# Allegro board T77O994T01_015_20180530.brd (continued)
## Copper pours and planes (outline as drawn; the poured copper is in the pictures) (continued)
(no net) on P07: 28.72,23 28.72,55.58 47.07,73.93 86.34,73.93 88.68,71.59 94.42,71.59 95.02,72.2 95.56,72.2 96.31,71.45 105.4,71.45 106.19,70.66 106.19,61.86 104.28,59.96 102.38,59.96 99.2,63.13 93.49,63.13 91.58,61.23 91.58,40.8 96.61,35.77 96.61,29.88 94.93,28.19 91.57,28.19 82.06,18.68 37.89,18.68 37.55,18.84 37.21,18.68 33.04,18.68
(no net) on P07: 123.11,40 123.34,39.77 123.34,38.86 123.08,38.6 122.29,38.6 121.47,37.78 121.3,37.78 121.02,37.5 121.02,37.33 120.04,36.34 120.04,36.34 119.86,36.16 119.86,30.42 119.85,30.41 119.85,29.27 119.27,28.7 108.86,28.7 105.15,32.4 98.7,32.4 98.44,32.65 98.44,33.54 98.67,33.78 109.11,33.78 109.62,33.27 117.5,33.27 118.03,33.8 118.03,36.14 118.92,37.03 118.94,37.03 119.58,37.66 120.09,37.66 121.18,38.75 121.18,39.95 121.23,40 ; 2 cut-outs
(no net) on P07: 106.75,23.8 105.87,24.68 106.11,24.68 106.11,24.96 105.75,24.96 105.75,24.8 104.57,25.98 104.54,25.98 99.89,30.62 98.82,30.62 98.57,30.88 98.57,31.89 98.82,32.15 104.9,32.15 108.72,28.33 108.73,28.32 119.4,28.32 120.29,29.2 120.29,35.76 121.05,36.52 121.05,37.08 121.43,37.46 121.69,37.46 122.58,36.57 122.58,36.11 123.16,35.53 123.16,31.97 123.26,31.87 123.26,26.3 120.76,23.8 ; 3 cut-outs
(no net) on P07: 47.13,74.44 43.72,71.03 32.86,71.03 31.31,72.58 31.31,80.84 32.53,82.06 75.97,82.06 80.62,77.4 86.16,77.4 89.87,73.7 91.16,73.7 91.57,73.29 94.95,73.29 95.33,73.67 102.62,73.67 104.19,75.24 113.29,75.24 114.02,74.51 114.02,61.94 115.19,60.77 116.49,60.77 120.22,57.03 120.22,52.18 119.23,51.19 118.24,51.19 118.06,51.37 118.06,55.81 117.5,56.37 111.59,56.37 106.71,61.25 106.71,70.6 105.73,71.57 96.61,71.57 95.79,72.4 94.85,72.4 94.24,71.79 88.95,71.79 86.31,74.44 ; 2 cut-outs
(no net) on P07: 107.85,50.31 118.26,50.31 118.51,50.06 118.51,45.04 114.1,40.63 103.02,40.63 102.76,40.38 102.76,40.36 101.62,39.22 94.63,39.22 93.68,40.17 93.68,54.65 94.29,55.26 98.7,55.26 99.14,54.81 99.14,54.8 102.31,51.63 102.31,48.11 102.56,47.86 105.4,47.86
(no net) on P07: 75.52,82.78 20.56,82.78 15.79,78.01 15.79,53.75 17.87,51.67 25.64,51.67 26.81,50.5 26.81,22.13 26.47,21.79 24.92,21.79 22.64,19.51 22.64,19.16 19.33,15.85 19.33,13.3 19.83,12.8 19.83,6.62 16.02,6.62 16.02,13.4 15.24,14.18 15.24,15.38 15.25,15.39 15.25,17.55 12.21,20.59 2.05,30.75 2.05,77.74 18.81,94.5 78.23,94.5 79.28,93.46 79.28,86.6 76.15,83.47 75.52,82.84
(no net) on T08: 117.32,50.26 114.68,50.26 114.68,48.97 117.32,48.97
(no net) on T08: 121.59,37.94 121.28,37.94 121.08,38.15 121.08,38.68 121.13,38.73 121.13,39.16 121.08,39.21 121.08,39.75 121.26,39.92 123.16,39.92 123.24,39.85 123.24,39.49 123.03,39.29 122.8,39.29 121.89,38.37 121.89,38.25
(no net) on T08: 118.08,55.21 114.68,55.21 114.68,53.83 114.73,53.77 116.02,53.77 116.3,53.49 116.3,52.16 115.99,51.86 115.74,51.86 115.6,51.71 115.6,51.15 115.44,51 114.78,51 114.68,50.89 114.68,50.64 118.08,50.64
(no net) on T08: 121.13,40.41 121.31,40.23 123.21,40.23 123.49,39.95 123.49,39.36 121.76,37.64 121.33,37.64 120.87,37.18 120.87,36.75 120.32,36.19 120.32,33.75 120.57,33.5 122.35,33.5 122.36,33.51 122.72,33.51 122.98,33.78 122.98,36.06 122.97,36.08 122.97,36.58 123.22,36.84 123.5,36.84 124.4,37.74 124.4,38.02 124.53,38.15 124.53,39.29 124.89,39.64 124.89,40.66 124.61,40.94 121.2,40.94 121.13,40.86
(no net) on T08: 197.58,9.69 195.04,12.23 190.59,12.23 189.74,11.37 186.37,11.37 186.15,11.59 186.15,17.31 195.04,26.2 196.94,26.2 198.21,24.93 199.48,24.93 201.39,26.83 201.39,32.55 198.85,35.09 193.77,35.09 191.86,36.99 191.86,38.9 192.5,39.53 197.58,39.53 198.85,38.26 201.39,38.26 205.2,34.45 205.2,27.47 198.85,21.12 198.85,12.23 199.48,11.59 199.48,9.69 ; 1 cut-out
(no net) on T08: 123.74,42.51 123.49,42.26 123.49,41.24 123.62,41.12 124.86,41.12 125.19,40.79 125.19,39.62 124.67,39.1 124.67,37.65 123.29,36.27 123.29,32.8 123.41,32.67 124.05,32.67 124.43,33.05 124.43,35.97 125.82,35.97 126.31,36.46 126.31,38.29 126.88,38.86 127.43,38.86 128.09,39.52 128.76,39.52 129.13,39.89 129.13,41.18 127.79,42.51
(no net) on T08: 187.42,34.31 198.99,34.31 200.75,32.55 200.75,26.83 199.48,25.56 198.21,25.56 196.94,26.83 195.04,26.83 191.86,23.66 187.42,23.66 186.78,24.29 186.78,33.67
(no net) on T08: 143.49,82.71 163.4,82.71 167.72,87.03 197.69,87.03 198.96,88.3 198.96,94.14 198.45,94.65 142.19,94.65 141.94,94.4 141.94,93.38 142.93,92.4 142.93,83.28
(no net) on T08: 115.74,53.44 116,53.18 116,52.53 115.41,51.95 115.41,51.41 115.31,51.32 114.8,51.32 114.6,51.11 114.6,49.96 114.38,49.74 114.38,48.8 108.64,43.07 101.04,43.07 100.79,43.32 100.79,43.98 101.04,44.23 107.01,44.23 110.19,47.41 110.19,52.06 111.57,53.44
(no net) on T08: 67.56,59.07 73.79,59.07 74.55,58.31 74.55,50.56 72.52,48.53 67.82,48.53 67.18,49.17 67.18,58.69
(no net) on T08: 114.96,48.67 116.05,48.67 116.3,48.42 116.3,42.71 114.9,41.31 111.09,41.31 108.73,38.95 101.22,38.95 100.8,39.37 100.8,39.9 102.62,41.72 108.01,41.72
(no net) on T08: 91.89,46.52 96.23,46.52 96.69,46.06 96.69,44.33 91.49,39.13 87.1,39.13 81.69,33.72 81.69,31.95 79.81,30.06 78.41,30.06 71.66,23.32 52.39,23.32 51,24.7 39.65,24.7 38.91,25.44 32.18,25.44 31.57,26.05 27.53,26.05 26.39,24.91 21.35,24.91 21.05,25.21 21.05,35.42 21.71,36.08 37.19,36.08 41.4,31.87 47.29,31.87 49.35,29.81 65,29.81 66.17,28.64 69.85,28.64 70.54,29.33 70.54,31 83.47,43.94 89.32,43.94
(no net) on T08: 10.13,68.23 4.41,73.95 3.78,73.95 3.4,73.57 3.4,65.95 5.43,63.91 9.87,63.91 10.13,64.17
(no net) on G09: 123.13,0.63 123.13,10.75 122.67,11.87 121.55,12.34 99.95,12.34 98.83,11.87 98.37,10.75 98.37,4.11 28.44,4.11 28.44,10.3 26.85,11.88 25.26,10.3 25.26,4.11 15.33,4.11 15.33,12.34 1,12.34 0.74,12.44 0.64,12.7 0.64,95.2 0.74,95.46 1,95.56 209,95.56 209.26,95.46 209.37,95.2 209.37,1 209.26,0.74 209,0.63 ; 18 cut-outs
(no net) on G09: 167.48,58.96 167.86,58.58 168.48,58.58 168.62,58.72 179.78,58.72 179.92,58.58 180.29,58.58 180.43,58.72 183.86,58.72 185.13,57.44 185.13,46.13 183.86,44.86 180.05,44.86 179.29,45.63 173.59,45.63 172.44,44.48 167.59,44.48 167.59,44.48 164.55,44.48 164.54,44.49 152.73,44.49 152.48,44.23 152.35,44.23 152.35,44.23 144.62,44.23 143.6,43.21 138.02,43.21 136.22,45.01 136.22,49.18 136.99,49.95 136.99,50.33 137.75,51.09 137.75,51.22 138.26,51.72 138.26,52.23 139.4,53.37 141.19,53.37 142.21,54.39 142.21,56.55 144.62,58.96
(no net) on T10: 119.55,42.9 119.68,43.02 126,43.02 126.59,42.43 126.59,39.75 126.31,39.47 125.14,39.47 124.63,38.96 124.63,37.31 124.51,37.18 124.25,37.18 124.13,37.05 124.13,36.29 124,36.16 123.49,36.16 123.36,36.04 123.36,34.16 122.32,33.12 119.81,33.12 119.68,33.24 119.68,36.55 120.09,36.95 120.54,36.95 121.18,37.59 121.18,38.48 120.93,38.73 119.91,38.73 119.55,39.09
(no net) on T10: 120.8,38.35 117.5,38.35 116.99,37.84 113.51,37.84 110.86,35.19 110.86,33.29 112.78,31.36 117.5,31.36 119.27,33.14 119.27,36.57 120.04,37.33 120.42,37.33 120.93,37.84 120.93,38.22
(no net) on T10: 189.32,83.35 189.32,82.08 188.69,81.44 186.15,81.44 185.39,82.2 159.34,82.2 158.84,82.71 158.84,82.72 158.21,83.35 158.21,86.52 158.84,87.16 185.51,87.16
(no net) on T10: 139.78,94.78 195.07,94.78 200.41,89.44 200.41,86.25 201.93,84.73 202.14,84.73 207.6,79.26 207.6,71.41 206.33,70.14 202.14,70.14 199.09,73.19 199.09,84.74 194.14,89.7 184.23,89.7 182.58,91.35 144.99,91.35 143.72,92.62 140.8,92.62 139.65,93.76 139.65,94.65
(no net) on T10: 37.61,70.26 44.62,70.26 49.95,64.93 93.11,64.93 98.82,59.22 98.82,53.45 98.32,52.94 45.23,52.94 36.82,61.35 36.82,69.48
(no net) on T10: 117.9,55.19 114.83,55.19 114.58,54.93 114.58,53.56 114.63,53.51 116,53.51 116.15,53.36 116.15,52.01 115.92,51.79 115.72,51.79 115.72,51.18 115.54,51 114.96,51 114.93,50.97 114.93,50.57 117.88,50.57 118.18,50.87 118.18,51.05 117.9,51.33
(no net) on T10: 187.09,88.79 193.75,88.79 198.14,84.41 198.14,60.49 199.48,59.14 199.48,44.61 198.15,43.28 189.9,43.28 189.83,43.34 175.35,43.34 174.72,43.98 174.72,59.85 177.88,63.01 185.67,63.01 186.33,63.66 186.33,80.42 186.96,81.06 189.07,81.06 189.83,81.82 189.83,83.85 186.75,86.93 186.75,88.46
(no net) on T10: 117.12,50.24 114.75,50.24 114.75,48.99 117.12,48.99
(no net) on T10: 160.75,12.86 187.42,12.86 188.05,13.5 196.31,13.5 199.48,10.32 199.48,7.78 194.95,3.24 164.65,3.24 160.11,7.78 160.11,12.23
(no net) on G11: 123.13,0.63 123.13,10.75 122.67,11.87 121.55,12.34 99.95,12.34 98.83,11.87 98.37,10.75 98.37,4.11 28.44,4.11 28.44,10.3 26.85,11.88 25.26,10.3 25.26,4.11 15.33,4.11 15.33,12.34 1,12.34 0.74,12.44 0.64,12.7 0.64,95.2 0.74,95.46 1,95.56 209,95.56 209.26,95.46 209.37,95.2 209.37,1 209.26,0.74 209,0.63 ; 18 cut-outs
(no net) on G11: 144.75,58.96 167.48,58.96 168.24,58.2 172.18,58.2 173.45,56.93 173.45,44.99 172.69,44.23 164.29,44.23 164.04,44.49 152.73,44.49 152.73,44.48 152.48,44.23 145.89,44.23 144.49,45.63 144.49,58.71
Net_1 on TOP (solid shape): outline of 195 points within 13.53,87.28 17.65,91.4
Net_1 on TOP (solid shape): outline of 195 points within 192.17,84.11 196.28,88.22
Net_1 on TOP (solid shape): outline of 195 points within 192.78,15.07 196.89,19.18
Net_1 on BOTTOM (solid shape): outline of 195 points within 13.53,87.28 17.65,91.4
Net_1 on BOTTOM (solid shape): outline of 195 points within 192.17,84.11 196.28,88.22
Net_1 on BOTTOM (solid shape): outline of 195 points within 192.78,15.07 196.89,19.18
P_CPU_DR1_LX_40 on TOP (solid shape): 109.49,92.47 109.49,87.77 109.36,87.65 107.08,87.65 106.57,88.15 106.57,89.42 105.71,90.28 102.39,90.28 102.39,92.73 109.24,92.73
P_CPU_DR1_LX_40 on TOP (solid shape): 103.04,92.37 102.49,92.37 102.49,92.25 103.04,92.25 103.04,91.87 102.49,91.87 102.49,91.75 103.04,91.75 103.04,91.37 102.49,91.37 102.49,91.25 103.04,91.25 103.04,90.87 102.49,90.87 102.49,90.75 103.04,90.75 103.04,90.37 102.49,90.37 102.49,90.25 103.04,90.25 103.04,89.87 102.13,89.87 102.13,92.75 103.04,92.75
P_CPU_DR2_LX_40 on TOP (solid shape): 109.49,82.69 109.49,78.63 109.36,78.5 107.33,78.5 105.58,80.25 102.39,80.25 102.39,82.82 109.36,82.82
P_CPU_DR2_LX_40 on TOP (solid shape): 103.04,82.34 102.49,82.34 102.49,82.22 103.04,82.22 103.04,81.84 102.49,81.84 102.49,81.72 103.04,81.72 103.04,81.34 102.49,81.34 102.49,81.22 103.04,81.22 103.04,80.83 102.49,80.83 102.49,80.72 103.04,80.72 103.04,80.33 102.49,80.33 102.49,80.22 103.04,80.22 103.04,79.83 102.13,79.83 102.13,82.72 103.04,82.72
P_DDR4_DR1_LX_40 on BOTTOM (solid shape): 199.39,66.87 199,66.87 199,67.43 198.89,67.43 198.89,66.87 198.5,66.87 198.5,67.43 198.39,67.43 198.39,66.87 198,66.87 198,67.43 197.89,67.43 197.89,66.87 197.5,66.87 197.5,67.43 197.39,67.43 197.39,66.87 197,66.87 197,67.43 196.89,67.43 196.89,66.87 196.5,66.87 196.5,67.79 199.39,67.79
P_DDR4_DR1_LX_40 on BOTTOM (solid shape): 198.98,67.71 199.07,67.66 199.08,67.57 199.05,67.45 199.03,67.33 199.03,66.28 199.17,65.42 200.02,65.25 200.03,65.25 200.07,65.25 200.13,65.19 205.06,65.19 205.06,65.14 205.22,64.69 205.58,64.37 205.58,62.79 205.18,62.39 196.96,62.39 196.47,62.88 196.47,67.58 196.6,67.71
P_DDR4_VIN_SHAPE on BOTTOM (solid shape): 196.89,72.05 197,72.05 197,72.6 197.39,72.6 197.39,72.05 197.5,72.05 197.5,72.6 197.89,72.6 197.89,72.05 198,72.05 198,72.6 198.39,72.6 198.39,72.05 198.5,72.05 198.5,72.6 198.89,72.6 198.89,72.05 199,72.05 199,72.6 199.36,72.6 199.36,71.69 196.5,71.69 196.5,72.6 196.89,72.6
P_DDR4_VIN_SHAPE on BOTTOM (solid shape): 196.89,72.05 197,72.05 197,72.6 197.39,72.6 197.39,72.05 197.5,72.05 197.5,72.6 197.89,72.6 197.89,72.05 198,72.05 198,72.6 198.39,72.6 198.39,72.05 198.5,72.05 198.5,72.6 198.89,72.6 198.89,72.05 199,72.05 199,72.6 199.39,72.6 199.39,71.69 196.5,71.69 196.5,72.6 196.89,72.6
P_DDR4_VIN_SHAPE on BOTTOM (solid shape): 196.29,82.71 196.29,80.47 196.29,80.3 196.98,79.62 196.98,76.98 193.93,76.98 193.93,76.6 196.98,76.6 197.23,76.34 197.23,76.32 196.86,75.95 196.86,75.7 196.81,75.64 196.74,75.51 196.7,75.39 196.69,75.34 196.67,75.25 196.67,74.97 196.68,74.91 196.69,74.82 196.71,74.72 196.75,74.63 196.78,74.56 196.83,74.49 196.88,74.43 196.92,74.38 196.97,74.33 197.07,74.26 197.13,74.22 197.2,74.18 197.27,74.15 197.38,74.12 197.47,74.11 197.55,74.11 198.75,74.11 199,73.86 199,73.8 199.01,73.65 199.06,73.51 199.06,72.14 199.07,72.03 199.1,71.93 199.09,71.83 199,71.79 195.61,71.79 195.61,71.87 193.01,71.87 193.01,71.78 192.92,71.78 192.79,71.64 192.79,71.5 192.63,71.35 192.63,69.69 192.13,69.18 191.03,69.18 190.98,69.23 190.98,78.38 191.67,79.07 191.67,83.15 191.68,83.16 191.9,83.31 192.05,83.53 192.05,83.53 195.48,83.53
P_DDR4_VREF_10 on T08 (solid shape): outline of 1368 points within 186.78,23.66 200.75,34.31
VFLTP1P05_CPU_VCCKRLCPLL on TOP (solid shape): 101.86,44.54 101.86,42.02 101.51,41.67 98.57,41.67 98.57,41.78 99.03,41.78 99.28,42.03 99.03,42.29 98.57,42.29 98.57,44.59 98.7,44.72 101.67,44.72
VFLTP1P05_CPU_VCCKRLCPLL on T08 (solid shape): outline of 483 points within 100.79,43.07 115.92,53.44
VFLTP1P05_CPU_VCCSCPLL on TOP (solid shape): 101.62,39.76 101.62,37.59 99.1,37.59 98.57,38.11 98.57,38.63 99.03,38.63 99.28,38.88 99.03,39.14 98.57,39.14 98.57,39.88 98.72,40.02 101.36,40.02
VFLTP1P05_CPU_VCCSCPLL on T08 (solid shape): outline of 830 points within 100.8,38.95 116.3,48.67
VFLTP1P05_PCH_VCCCLK on BOTTOM (solid shape): outline of 201 points within 106.82,32.38 114.7,37.97
VFLTP1P05_PCH_VCCCLK on T10 (solid shape): outline of 842 points within 110.86,31.36 120.93,38.35
VP0P6_DDR4_VTT on TOP (solid shape): outline of 461 points within 185.83,81.72 199.85,94.62
VP0P6_DDR4_VTT on BOTTOM (solid shape): 188.8,93.16 188.8,91.41 188.72,91.33 187.45,91.33 187.33,91.46 185.94,91.46 185.82,91.58 185.82,92.22 186.96,93.36 188.59,93.36
VP0P6_DDR4_VTT on BOTTOM (solid shape): 189.58,81.44 188.32,81.44 187.87,81.89 187.87,82.77 187.27,83.36 186.96,83.36 186.92,83.36 186.87,83.35 186.08,83.35 186.04,83.37 186.02,83.4 186.02,83.43 186.04,83.47 186.08,83.48 187.03,83.48 187.21,83.66 187.24,83.69 187.27,83.71 187.54,83.98 189.58,83.98
VP0P6_DDR4_VTT on T10 (solid shape): outline of 564 points within 158.21,81.44 189.32,87.16
VP0P6_DDR4_VTT_REFIN on TOP (solid shape): 186.96,91.07 186.96,89.21 186.89,89.21 186.89,88.71 186.83,88.66 185.54,88.66 185.54,89.21 185.44,89.21 185.44,89.42 185.04,89.42 185.04,89.42 184.63,89.23 184.54,88.79 184.53,88.7 184.45,88.66 184.29,88.66 184.26,88.69 184.24,88.68 183.99,88.68 183.99,89.7 184.5,90.2 185.51,90.2 185.82,90.51 185.82,90.6 185.83,90.6 185.83,91.08 185.94,91.2 186.83,91.2
VP1P2_DDR4_VDD on TOP (solid shape): 189.34,90.73 189.89,90.73 190,90.63 190,89.03 190.15,88.88 191.55,88.88 191.89,89.21 192.74,89.21 192.84,89.11 192.84,88.49 191.23,86.88 186.45,86.88 186.33,87.01 186.33,88.15 186.96,88.15 187.32,88.51 187.32,91.09 187.27,91.14 187.27,91.2 186.96,91.51 185.94,91.51 185.94,91.58 186.07,91.71 188.36,91.71
VP1P2_DDR4_VDD on TOP (solid shape): outline of 98 points within 150.74,43.72 168.72,60.32
VP1P2_DDR4_VDD on TOP (solid shape): outline of 125 points within 139.44,45.24 142.32,56.28
VP1P2_DDR4_VDD on TOP (solid shape): outline of 1829 points within 173.78,44.42 200.12,60.18
VP1P2_DDR4_VDD on BOTTOM (solid shape): outline of 117 points within 185.47,44.42 205.58,59.09
VP1P2_DDR4_VDD on BOTTOM (solid shape): outline of 6685 points within 132.31,41.18 177.26,60.61
VP1P2_DDR4_VDD on G02 (solid shape): outline of 9128 points within 135.35,42.45 185.13,60.61
VP1P2_DDR4_VDD on G04 (solid shape): outline of 9224 points within 135.35,42.45 185.13,61.05
VP1P2_DDR4_VDD on P06 (solid shape): outline of 9682 points within 135.35,41.31 198.07,61.12
VP1P2_DDR4_VDD on P07 (solid shape): outline of 8951 points within 135.35,42.45 199.74,60.36
VP1P2_DDR4_VDD on G09 (solid shape): outline of 7032 points within 136.22,43.21 185.13,58.96
VP1P2_DDR4_VDD on T10 (solid shape): outline of 5841 points within 174.72,43.28 199.48,88.79
VP1P2_DDR4_VDD on G11 (solid shape): outline of 3037 points within 144.49,44.23 173.45,58.96
VP1P3 on TOP (solid shape): 57.03,71.64 57.25,71.64 57.25,71.62 57.81,71.62 57.81,71.64 61.85,71.64 62.1,71.39 62.1,70.25 62.06,70.24 61.81,70.11 61.72,69.85 61.69,69.77 61.62,69.74 56.52,69.74 56.12,70.13 54.96,70.13 54.7,70.39 54.7,71.79 56.88,71.79
VP1P3 on T05 (solid shape): outline of 5717 points within 50.31,50.54 114.58,94.25
VP1P05 on TOP (solid shape): 29.81,32.29 29.81,30.77 29.69,30.64 27.65,30.64 27.15,31.15 26.93,31.15 26.93,31.16 26.37,31.16 26.37,31.15 26.26,31.15 26.13,31.28 26.13,32.16 26.38,32.42 29.69,32.42
VP1P05 on TOP (solid shape): 115.67,52.23 115.77,52.24 116.34,52.24 116.39,52.19 116.47,52.11 116.51,52.11 116.74,52.1 116.92,52.24 117.1,52.24 117.17,52.17 117.2,52.14 117.24,52.12 117.46,51.89 117.47,51.89 117.55,51.75 117.69,51.67 117.7,51.66 118.21,51.15 118.21,50.62 118.08,50.49 117.05,50.49 116.86,50.68 116.57,50.68 116.4,50.85 116.05,50.85 115.95,50.74 115.74,50.74 115.64,50.85 115.26,50.85 115.13,50.72 115.01,50.72 114.96,50.77 114.96,51.25 114.98,51.28 115.21,51.28 115.21,51.38 115.31,51.52 115.35,51.68 115.35,51.95 115.32,51.98 115.32,52.22 115.34,52.24 115.57,52.24
VP1P05 on TOP (solid shape): 94.7,42.76 94.7,42.29 94.31,42.29 94.05,42.03 94.31,41.78 94.7,41.78 94.7,39.14 94.31,39.14 94.05,38.88 94.31,38.63 94.7,38.63 94.7,38.08 94.45,37.84 92.04,37.84 91.23,37.03 91.23,31.11 89.37,31.11 89.37,33.65 88.28,33.65 88.03,33.9 87.81,33.9 87.8,33.91 87.59,33.95 87.39,33.9 86.25,33.9 84.71,35.45 84.71,37.99 86.36,39.64 89.53,39.64 92.96,43.07 94.39,43.07
VP1P05 on TOP (solid shape): 116.75,54.96 117.03,54.84 117.32,54.96 117.55,54.96 118.03,54.48 118.03,54.39 117.55,53.91 117.44,53.6 117.6,53.31 117.64,53.23 117.6,53.15 117.53,53.08 117.48,53 117.39,53 117.03,53.23 116.68,53.01 116.67,52.98 116.6,52.98 116.59,53.01 116.41,53.18 116.17,53.22 116.08,53.24 116.05,53.32 116.05,54.07 115.97,54.15 115.04,54.15 114.9,54.2 114.76,54.18 114.73,54.17 114.63,54.27 114.63,54.68 114.86,54.92 115.22,54.92 115.22,54.92 115.36,54.89 115.49,54.92 115.5,54.92 116.04,54.89 116.05,54.88 116.3,54.84 116.52,54.96
VP1P05 on TOP (solid shape): outline of 282 points within 84.71,52.09 101.36,61.89
VP1P05 on BOTTOM (solid shape): outline of 145 points within 9.11,61.37 12.29,70.26
VP1P05 on BOTTOM (solid shape): outline of 236 points within 138.78,77.25 143.65,84.09
VP1P05 on BOTTOM (solid shape): outline of 338 points within 111.51,46.24 118.26,54.83
VP1P05 on BOTTOM (solid shape): outline of 361 points within 112.72,42.31 117.8,50.18
VP1P05 on BOTTOM (solid shape): outline of 6770 points within 83.31,31.02 123.34,76.74
VP1P05 on T03 (solid shape): 117.12,50.11 117.12,49.14 116.99,49.02 114.96,49.02 114.83,49.14 114.83,50.16 114.91,50.24 116.99,50.24
VP1P05 on T03 (solid shape): outline of 244 points within 114.58,50.6 117.93,54.99
VP1P05 on T03 (solid shape): outline of 2308 points within 94.23,36.16 125.17,57.55
VP1P05 on T05 (solid shape): 117.01,50.11 117.01,49.02 116.94,48.94 114.47,48.94 114.37,49.04 114.37,50.16 114.48,50.16 114.56,50.24 115.26,50.24 115.34,50.16 115.57,50.16 115.65,50.25 116.01,50.25 116.12,50.13 116.4,50.13 116.54,50.27 116.85,50.27
VP1P05 on T05 (solid shape): outline of 137 points within 197.82,30.01 205.18,33.94
VP1P05 on T05 (solid shape): outline of 178 points within 114.96,50.6 118.05,54.99
VP1P05 on T05 (solid shape): outline of 1636 points within 108.04,74.46 160.86,94.14
VP1P05 on T05 (solid shape): outline of 1688 points within 8.86,63.91 39.97,70.26
VP1P05 on P06 (solid shape): outline of 902 points within 93.36,50.67 117.88,62.25
VP1P05 on P06 (solid shape): outline of 1718 points within 94.94,39.22 118.51,55.26
VP1P05 on P07 (solid shape): outline of 888 points within 93.36,50.67 117.66,62.25
VP1P05 on P07 (solid shape): outline of 1813 points within 93.68,39.22 118.51,55.26
VP1P05 on P07 (solid shape): outline of 28408 points within 28.72,18.68 106.19,73.93
VP1P05 on T08 (solid shape): 117.32,48.97 116.29,48.97 116.2,49.06 114.8,49.06 114.76,49.02 114.71,49 114.68,49.05 114.68,50.26 117.32,50.26
VP1P05 on T08 (solid shape): outline of 153 points within 114.68,50.64 118.08,55.21
VP1P05 on T08 (solid shape): outline of 322 points within 3.4,63.91 10.13,73.95
VP1P05 on T10 (solid shape): 117.12,48.99 114.75,48.99 114.75,50.24 117.12,50.24
VP1P05 on T10 (solid shape): outline of 147 points within 114.58,50.57 118.18,55.19
VP1P05 on T10 (solid shape): outline of 5531 points within 36.82,52.94 98.82,70.26
VP1P05_LX_40 on TOP (solid shape): 80.82,58.94 80.82,58.16 80.82,58.16 80.82,57.24 80.84,57.23 80.84,53.67 80.62,53.46 80.62,51.86 77.8,51.86 77.8,52.8 78.11,53.1 78.11,58.94 78.23,59.07 80.7,59.07
VP1P05_LX_40 on TOP (solid shape): 78.21,52.24 78.33,52.24 78.33,52.79 78.71,52.79 78.71,52.24 78.83,52.24 78.83,52.79 79.21,52.79 79.21,52.24 79.33,52.24 79.33,52.79 79.71,52.79 79.71,52.24 79.83,52.24 79.83,52.79 80.21,52.79 80.21,52.24 80.33,52.24 80.33,52.79 80.71,52.79 80.71,51.88 77.83,51.88 77.83,52.79 78.21,52.79
VP1P5_PCH on TOP (solid shape): 50.37,73.31 50.37,72.43 50.39,72.41 50.39,70.06 50.24,69.76 50.39,69.46 50.39,67.58 50.14,67.33 49.63,67.33 49.53,67.22 49.48,67.22 49.48,67.17 49.43,67.12 49.28,67.12 49.28,67.07 49.26,67.07 49.26,67.06 48.57,66.36 48.34,66.36 48.34,66.4 47.36,66.4 47.35,66.41 47.35,67.2 47.75,67.6 47.75,68.21 47.75,68.21 47.75,69.97 47.96,69.97 47.96,71.8 47.75,71.8 47.75,73.21 47.82,73.28 47.86,73.24 48.24,73.12 48.53,73.4 48.54,73.44 50.24,73.44
VP1P05_PCH on TOP (solid shape): 103.01,35.19 103.01,31.77 101.7,30.45 97.38,30.45 96.95,30.88 96.61,30.88 96.42,30.93 96.23,30.88 94.08,30.88 94.08,30.96 93.16,30.96 93.11,30.94 93.05,31 93.05,31.44 92.34,32.15 92.31,32.15 92.31,32.15 91.55,32.15 91.55,33.9 91.59,33.99 91.69,34 91.96,33.98 92.19,34.12 92.25,34.15 92.32,34.13 92.61,34.05 92.86,34.19 92.94,34.23 93.02,34.19 93.37,34.05 93.67,34.27 93.69,34.31 96.41,34.31 97.39,35.28 97.48,35.19 98.04,35.19 98.04,35.74 97.94,35.84 98.19,36.08 102.12,36.08
VP1P05_PCH on BOTTOM (solid shape): 97.55,36.06 97.65,36 97.62,35.89 97.48,35.74 97.48,35.19 98.04,35.19 98.54,35.69 98.56,35.68 98.95,35.77 99.21,36.06 102.51,36.06 103.01,35.55 103.01,35.07 102.56,35.07 102.3,34.81 102.56,34.56 103.01,34.56 103.01,31.13 102.38,30.5 100.77,30.5 100.61,30.66 97.69,30.66 97.53,30.5 97.36,30.5 96.31,31.54 96.11,31.54 96.1,31.55 94.97,31.55 94.84,31.68 94.84,31.92 94.1,31.92 94.01,32.01 94.01,35.86 94.21,36.06
VP1P05_PCH on BOTTOM (solid shape): outline of 138 points within 118.02,37.46 120.77,39.94
VP1P05_PCH on T03 (solid shape): 102.44,31.91 102.44,31.28 101.81,30.64 98.76,30.64 98.5,30.9 98.5,31.51 98.71,31.75 98.7,32.07 98.69,32.1 98.76,32.17 102.19,32.17
VP1P5_PCH on T05 (solid shape): outline of 8256 points within 47.77,34.92 128.04,89.17
VP1P05_PCH on P06 (solid shape): outline of 912 points within 98.44,33.65 120.85,40.53
VP1P05_PCH on P06 (solid shape): outline of 1123 points within 98.52,28.7 123.26,40
VP1P05_PCH on P06 (solid shape): outline of 1849 points within 98.57,23.76 125.27,41.78
VP1P05_PCH on P07 (solid shape): outline of 896 points within 98.44,33.65 120.85,40.53
VP1P05_PCH on P07 (solid shape): outline of 1110 points within 98.52,28.7 123.34,40
VP1P05_PCH on P07 (solid shape): outline of 1487 points within 98.57,23.8 123.26,37.46
VP1P05_PCH on T08 (solid shape): 123.24,39.85 123.24,39.49 123.05,39.31 122.98,39.3 122.93,39.29 122.8,39.29 121.89,38.37 121.89,38.25 121.59,37.94 121.28,37.94 121.08,38.15 121.08,38.68 121.13,38.73 121.13,39.16 121.08,39.21 121.08,39.75 121.26,39.92 123.16,39.92
VP1P05_PCH on T08 (solid shape): outline of 472 points within 120.32,33.5 124.89,40.94
VP1P05_VIN on TOP (solid shape): 80.62,45.98 80.59,45.95 79.29,45.95 79.16,45.83 79.16,45.41 79.4,45.18 80.24,45.18 80.24,45.17 80.39,45.03 80.39,44.09 80.77,43.7 82.3,43.7 82.42,43.58 82.42,39.89 82.04,39.51 80.14,39.51 79.38,40.28 78.11,40.28 73.41,44.97 73.41,47.64 73.66,47.9 77.24,47.9 77.32,47.97 80.62,47.97
VP1P05_VIN on TOP (solid shape): 80.71,47.06 80.33,47.06 80.33,47.62 80.21,47.62 80.21,47.06 79.83,47.06 79.83,47.62 79.71,47.62 79.71,47.06 79.33,47.06 79.33,47.62 79.21,47.62 79.21,47.06 78.83,47.06 78.83,47.62 78.71,47.62 78.71,47.06 78.33,47.06 78.33,47.62 78.21,47.62 78.21,47.06 77.83,47.06 77.83,47.98 80.71,47.98
VP1P05_VIN on BOTTOM (solid shape): 78.87,47.13 78.87,45.48 78.74,45.36 73.53,45.36 73.41,45.48 73.41,47.26 73.53,47.39 78.61,47.39
VP1P05_VREF_10 on T08 (solid shape): outline of 876 points within 67.18,48.53 74.55,59.07
VP1P7 on TOP (solid shape): 35.39,84.74 35.39,74.71 35,74.33 32.34,74.33 31.96,74.71 31.96,84.62 32.34,85 35.13,85
VP1P7 on TOP (solid shape): 61.21,78.12 61.21,75.58 60.96,75.33 58.17,75.33 57.91,75.07 57.15,75.07 56.12,74.05 55.7,74.05 55.7,74.05 54.75,74.05 54.7,74.1 54.7,75.16 54.82,75.29 54.88,75.45 54.88,75.47 57.66,78.25 61.09,78.25
VP1P7 on TOP (solid shape): 44.26,72.43 44.28,72.43 44.66,72.04 44.66,69.79 44.88,69.56 44.88,68.97 44.91,68.97 44.91,68.92 44.99,68.85 44.99,68.77 45.07,68.77 45.24,68.6 45.24,67.46 45.23,67.46 45.23,66.4 44.17,66.4 44.12,66.44 43.81,66.76 43.83,66.8 43.87,67.26 43.49,67.52 43.47,67.52 43.39,67.61 43.39,68.72 41.66,70.45 41.66,70.64 41.7,70.69 41.7,71.24 41.7,71.25 41.7,71.83 41.7,72.32 42.04,72.66 44.02,72.66
VP1P7 on P07 (solid shape): outline of 5966 points within 31.31,51.19 120.04,82.06
VP1P7_SW on TOP (solid shape): 34.88,90.84 34.88,87.28 34.55,86.96 31.16,86.96 30.78,87.34 29.43,87.34 29.41,87.33 29.36,87.36 29.36,89.23 29.37,89.24 29.48,89.3 29.58,89.38 29.99,89.79 29.99,89.86 30.18,90.05 30.18,90.55 30.19,90.56 30.23,90.71 30.25,90.82 30.26,90.9 30.26,91.17 30.38,91.3 31.27,91.3 31.27,91.37 34.34,91.37
VP1P7_VIN on TOP (solid shape): 21.42,92.35 21.42,89.86 21.59,89.69 22.89,89.69 22.9,89.69 26.35,89.69 26.47,89.57 26.99,89.57 27.22,89.35 27.22,88.84 27.23,88.73 27.25,88.63 27.24,88.54 27.16,88.49 27,88.49 27,88 26.97,87.98 26.97,87.72 26.85,87.6 24.43,87.6 24.41,87.62 23.75,87.62 23.39,87.27 19.66,87.27 19.34,87.58 19.34,92.12 19.81,92.58 21.19,92.58
VP1P8_CPU_VCCIN on TOP (solid shape): outline of 564 points within 114.32,44.03 130.91,94.5
VP1P8_CPU_VCCIN on BOTTOM (solid shape): outline of 1771 points within 114.57,44.01 132.9,91.84
VP1P8_CPU_VCCIN on T03 (solid shape): outline of 1093 points within 114.32,44.42 133.84,91.71
VP1P8_CPU_VCCIN on T05 (solid shape): outline of 2116 points within 114.32,44.46 130.07,91.71
VP1P8_CPU_VCCIN on P06 (solid shape): outline of 6860 points within 114.33,44.44 133.12,91.35
VP1P8_CPU_VCCIN on P07 (solid shape): outline of 5059 points within 114.31,44.44 133.12,92.75
VP2P5_DDR4_VPP on TOP (solid shape): 178.26,91.55 178.26,90.48 178.4,90.33 178.4,90.08 178.28,90.08 178.28,89.16 178.4,89.16 178.4,82.73 178.24,82.57 175.37,82.57 175.37,82.58 173.76,82.58 173.69,82.65 173.66,82.74 173.63,82.81 173.63,85.63 173.24,86.02 173.28,86.07 173.28,93.41 176.4,93.41
VP2P5_DDR4_VPP on BOTTOM (solid shape): 178.21,90.13 178.21,89.24 178.39,89.24 178.39,82.71 178.28,82.6 177.25,82.6 177.24,82.64 176.66,83.18 176,82.77 175.92,82.7 175.83,82.73 175.53,83.03 175.53,84.74 174.76,85.52 174.76,88.82 174.58,89 174.58,90.08 174.7,90.21 178.13,90.21
VP2P5_DDR4_VPP on T03 (solid shape): outline of 6555 points within 139.14,10.96 201.52,94.4
VP2P5_DDR4_VPP_SW on TOP (solid shape): 156.2,89.41 156.2,85.6 155.94,85.34 151.63,85.34 151.5,85.47 151.5,86.1 152.64,86.1 152.78,86.24 152.78,86.47 152.98,86.72 153.05,87.02 153.05,88.47 152.78,88.73 152.78,89.29 153.4,89.91 155.69,89.91
VP2P5_DDR4_VPP_VIN on TOP (solid shape): 150.28,89.99 151.2,89.99 151.2,89.99 151.25,89.94 151.25,89.42 151.24,89.41 151.21,89.19 151.24,88.97 151.25,88.96 151.25,88.03 149.48,88.03 149.07,87.63 149.07,86.22 149.04,86.14 148.86,85.96 144.51,85.96 144.22,86.25 144.22,89.69 144.58,90.04 150.28,90.04
VP2P5_DDR4_VPP_VOUT on TOP (solid shape): 172.09,93.26 172.09,84.98 171.47,84.37 171.2,84.37 171.11,84.42 171.12,84.53 170.46,85.79 169.81,84.53 169.82,84.42 169.73,84.37 167.97,84.37 167.97,84.97 167.65,85.29 167.65,85.32 167.12,85.82 166.83,85.15 166.83,85.04 166.75,84.99 165.72,84.99 165.67,85.01 165.62,85.01 164.3,85.01 163.74,84.46 163.67,84.51 163.61,84.6 163.67,84.69 163.81,84.81 163.89,84.97 163.89,84.99 164.3,85.39 164.32,85.39 164.55,86.02 163.92,85.79 163.92,85.77 163.67,85.52 163.66,85.53 163.2,85.98 161.36,85.98 160.87,85.5 160.87,84.08 160.4,84.08 159.86,84.63 159.59,84.63 159.2,84.28 159.51,83.85 159.52,83.85 159.74,83.63 159.6,83.48 159.36,83.71 159.07,83.83 158.78,83.69 158.7,83.65 158.62,83.69 158.3,83.83 157.99,83.65 157.92,83.6 157.83,83.63 157.74,83.7 157.64,83.73 157.6,83.74 157.6,89.67 158.13,90.21 168.7,90.21 169.24,90.74 169.24,93.16 169.65,93.56 171.78,93.56
VP2P5_DDR4_VPP_VOUT on BOTTOM (solid shape): 168.02,89.68 168.02,87.64 167.92,87.54 164.16,87.54 162.64,86.01 160.1,86.01 158.19,87.92 156.8,87.92 156.49,88.23 156.49,88.27 156.42,88.34 156.42,89.7 156.67,89.95 167.75,89.95
VP3P3 on TOP (solid shape): 144.91,4.72 141.99,4.72 141.99,8.91 144.91,8.91
VP3P3 on TOP (solid shape): 57.48,93.25 57.48,80.23 57.15,79.9 54.1,79.9 54.05,79.95 54.05,87.89 53.14,88.81 53.14,92.97 53.55,93.38 57.36,93.38
VP3P3 on TOP (solid shape): 62.87,32.15 62.87,29.03 62.79,28.95 62.74,28.85 62.74,28.84 62.61,28.72 59.56,28.72 59.31,28.97 59.31,32.15 59.56,32.4 62.61,32.4
VP3P3 on TOP (solid shape): 41.77,77.54 41.77,77.03 41.65,76.9 41.39,76.9 41.4,71.83 41.4,71.37 41.39,71.37 41.39,70.81 41.1,70.52 39.85,70.52 39.59,70.77 39.59,72.17 39.6,73.87 39.63,73.87 39.63,74.79 39.6,74.79 39.61,75.41 40.26,75.41 40.27,75.35 40.28,75.3 40.3,75.24 40.32,75.18 40.36,75.14 40.4,75.09 40.44,75.05 40.49,75.02 40.55,74.99 40.6,74.97 40.66,74.96 40.72,74.96 40.78,74.96 40.84,74.97 40.9,74.99 40.95,75.02 41,75.05 41.04,75.09 41.08,75.14 41.12,75.18 41.14,75.24 41.16,75.3 41.18,75.35 41.18,75.41 41.18,75.47 41.16,75.53 41.14,75.59 41.12,75.64 41.08,75.69 41.04,75.74 41,75.78 40.98,75.79 40.98,76.03 41.01,76.03 41.01,76.71 40.43,76.71 40.43,76.03 40.47,76.03 40.47,75.79 40.44,75.78 40.4,75.74 40.36,75.69 40.32,75.64 40.3,75.59 40.28,75.53 40.27,75.47 40.26,75.41 39.61,75.41 39.61,77.28 40,77.66 41.65,77.66
VP3P3 on BOTTOM (solid shape): outline of 352 points within 121.74,28.29 125.75,36.82
VP3P3 on T03 (solid shape): outline of 303 points within 47.72,77.25 55.9,87.92
VP3P3 on T03 (solid shape): outline of 3589 points within 124.55,2.07 168.62,22.39
VP3P3 on P06 (solid shape): outline of 37156 points within 8.4,17.41 127.81,88.55
VP3P3 on P07 (solid shape): outline of 374 points within 19.63,10.76 30.38,21.56
VP3P3 on T08 (solid shape): outline of 666 points within 123.29,32.67 129.13,42.51
VP3P3 on T08 (solid shape): outline of 1261 points within 186.15,9.69 205.2,39.53
VP3P3 on T10 (solid shape): outline of 3404 points within 160.11,3.24 199.48,13.5
VP3P3_A on TOP (solid shape): 55.12,66.69 55.12,64.69 54.96,64.53 51.69,64.53 51.56,64.66 51.56,66.69 51.69,66.82 54.99,66.82
VP3P3_A on TOP (solid shape): 40.79,79.41 40.79,79.27 40.79,79.26 40.76,79.11 40.79,78.95 40.79,78.94 40.79,77.98 36.08,77.98 35.84,78.22 35.84,79.29 36.09,79.54 40.67,79.54
VP3P3_A on BOTTOM (solid shape): outline of 636 points within 35.39,64.42 61.82,83.6
VP3P3_A on T03 (solid shape): outline of 2051 points within 116.16,32.48 127.91,42.9
VP3P3_A on P06 (solid shape): outline of 18220 points within 2.05,2.17 159.15,94.25
VP3P3_A on P07 (solid shape): outline of 8605 points within 85.23,2.32 157.75,43.81
VP3P3_A on T10 (solid shape): outline of 1550 points within 119.55,33.12 126.59,43.02
VP3P3_SW on TOP (solid shape): 51.26,92.75 51.26,88.43 51.13,88.3 50.16,88.3 49.79,88.3 49.39,87.91 49.39,86.05 48.76,86.05 48.76,88.76 48.79,88.81 48.82,88.88 48.86,88.96 48.88,89.07 48.89,89.16 48.9,89.22 48.9,89.5 48.88,89.59 48.87,89.63 48.83,89.76 48.76,89.88 48.76,92.28 49.36,92.87 51.13,92.87
VP3P3_VIN on TOP (solid shape): 45.55,90.67 45.55,89.06 46.74,87.86 46.74,87.75 46.82,87.68 46.82,85.89 45.75,85.89 45.75,85.97 44.17,85.97 44.17,85.89 36.91,85.89 36.66,86.14 36.66,88.51 36.86,88.71 39.85,88.71 40.18,89.04 40.18,91.23 40.36,91.41 44.81,91.41
VP5P0 on TOP (solid shape): 25.09,92.3 25.09,90.49 24.85,90.25 22.83,90.25 22.75,90.33 22.75,92.46 23.28,92.99 24.4,92.99
VP5P0 on TOP (solid shape): 26.26,46.01 26.26,42.96 26.01,42.71 21.81,42.71 21.56,42.96 21.56,45.89 22.07,46.39 25.88,46.39
VP5P0 on TOP (solid shape): 105.34,79.19 105.34,78.3 104.33,78.3 104.33,78.25 103.24,78.25 103.24,78.42 102.12,78.42 102.12,78.63 103.14,78.63 103.27,78.76 103.27,79.26 103.14,79.39 102.12,79.39 102.12,79.61 103.27,79.61 103.27,79.64 104.88,79.64
VP5P0 on TOP (solid shape): 105.3,89.42 105.31,89.42 105.31,88.5 105.27,88.46 104.33,88.46 104.33,88.41 103.24,88.41 103.24,88.45 102.23,88.45 102.23,88.66 103.39,88.66 103.39,89.3 103.27,89.42 102.23,89.42 102.23,89.64 103.27,89.64 103.27,89.68 105.05,89.68
VP5P0 on BOTTOM (solid shape): 25.61,45.12 25.61,42.96 25.23,42.58 22.18,42.58 21.8,42.96 21.8,45.25 22.05,45.5 25.23,45.5
VP5P0 on T03 (solid shape): outline of 953 points within 198.25,28.1 208.36,71.77
VP5P0 on T03 (solid shape): outline of 7364 points within 9.03,42.71 141.87,94.63
VP5P0 on T10 (solid shape): outline of 1560 points within 139.65,70.14 207.6,94.63
VP5P0_SW on TOP (solid shape): 14.42,52.11 14.42,48.3 14.16,48.05 9.98,48.05 9.98,48.24 9.72,48.24 9.72,48.81 10.86,48.81 10.99,48.94 10.99,49.06 11.26,49.33 11.26,49.63 11.26,49.68 11.26,49.73 11.26,52.26 11.62,52.62 13.91,52.62
VP5P0_VIN on TOP (solid shape): 9.48,52.61 9.48,52.12 9.46,52.11 9.46,50.74 6.91,50.74 6.58,50.41 6.58,48.43 6.27,48.12 2.03,48.12 1.97,48.19 1.97,52.2 2.16,52.39 5.89,52.39 6.14,52.64 9.45,52.64
VP5P0_VOUT on TOP (solid shape): 19.81,51.71 25.53,51.71 26.04,51.2 26.04,47.39 25.86,47.39 25.86,47.36 21.54,47.36 21.54,48.17 21.42,48.17 21.42,46.71 21.35,46.64 16.34,46.64 15.81,47.17 15.81,52.11 16.17,52.47 19.05,52.47
VP5P0_VOUT on BOTTOM (solid shape): 15.54,52.54 16.46,52.54 16.46,52.59 16.94,52.59 16.94,52.54 17.86,52.54 17.86,52.59 18.29,52.59 19.05,51.83 25.78,51.83 26.04,51.58 26.04,48.4 25.78,48.15 18.67,48.15 17.53,49.29 17.53,50.82 17.02,51.32 14.86,51.32 14.73,51.45 14.73,52.34 14.99,52.59 15.54,52.59
VP12P0 on TOP (solid shape): 193.52,23.15 193.52,21.37 193.26,21.12 191.61,21.12 191.36,21.37 191.36,23.15 191.61,23.4 193.26,23.4
VP12P0 on TOP (solid shape): 6.59,47.18 6.59,45.86 6.26,45.53 6.26,44.58 6.09,44.42 2.01,44.42 1.84,44.59 1.84,47.2 2.03,47.39 6.38,47.39
VP12P0 on TOP (solid shape): 39.6,92.95 39.6,91.52 39.6,89.6 39.5,89.5 37.12,89.5 36.94,89.68 36.94,92.96 37.08,93.11 39.45,93.11
VP12P0 on TOP (solid shape): 79.52,93.61 79.52,83.84 78.88,83.2 74.18,83.2 73.68,83.71 73.68,91.2 73.3,91.58 71.64,91.58 71.39,91.84 71.39,93.87 71.71,94.19 78.95,94.19
VP12P0 on TOP (solid shape): 149.15,84.19 149.15,82.06 148.67,81.58 144.48,81.58 143.84,82.21 143.84,82.57 143.03,83.38 143.03,83.51 143.03,83.51 143.03,84.49 143.29,84.75 148.59,84.75
VP12P0 on TOP (solid shape): 96.75,45.61 96.75,44.14 96.26,43.65 92.86,43.65 89.36,40.15 86.36,40.15 85.6,39.39 84.07,39.39 83.82,39.64 83.82,44.85 84.07,45.1 88.8,45.1 88.8,45.05 89.71,45.05 89.71,45.1 89.79,45.1 90.93,46.24 96.11,46.24
VP12P0 on TOP (solid shape): outline of 544 points within 10.51,4.1 24.86,36.13
VP12P0 on BOTTOM (solid shape): 79.52,93.61 79.52,83.84 78.88,83.2 74.18,83.2 73.68,83.71 73.68,91.2 73.3,91.58 71.64,91.58 71.39,91.84 71.39,93.87 71.71,94.19 78.95,94.19
VP12P0 on BOTTOM (solid shape): outline of 567 points within 11.27,4.1 24.86,36.36
VP12P0 on BOTTOM (solid shape): outline of 700 points within 141.95,79.66 200.5,94.62
VP12P0 on P06 (solid shape): outline of 3009 points within 70.82,84.87 199.47,94.52
VP12P0 on P07 (solid shape): outline of 4177 points within 141.81,21.37 208.36,94.52
VP12P0 on P07 (solid shape): outline of 8739 points within 2.05,6.62 79.28,94.5
VP12P0 on T08 (solid shape): outline of 2584 points within 141.94,82.71 198.96,94.63
VP12P0 on T08 (solid shape): outline of 2627 points within 21.05,23.32 96.69,46.52

Small or netless copper shapes (teardrops, artwork), in the pictures only: 1 on TOP, 1 on BOTTOM, 1 on T05, 1 on P06, 1 on P07, 1 on T08, 1 on T10

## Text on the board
DIMENSION: 210 | 96.2
PAGE_OUTLINE: 2018/01/19 | UNLESS OTHERWISE SPECIFIED | DIMENSIONS ARE IN INCHES | TOLERANCES ON; | 2 PL DECIMALS +/- .010 | 3 PL DECIMALS +/- .005 | ANGLES +/- 5 | FRACTIONS + | ISSUED | CAD          Mars | ENGRG        Jenna | SIGNATURES | DATE | SCALE | SIZE | FSCM NO | DWG NO | SHEET | REV | DESCRIPTION | REVISIONS | APPROVED | T77O994T01 | D | C | B | A | 7 | 6 | 5 | 4 | 3 | 2 | 1 | U | f | i | Space
DISPLAY_BOTTOM: CUTTING BURRS | CHAMFER EDGES | MUST BE FREE OF | SCALE 5.000 | DETAIL A | 64.4MIL | PACROSS PADS | 20.0 | 5.0 | 55MIL | 14 | DO NOT ADD | 17.PCB MATERIAL UL FLAMMABILITY RATING(94V-0 MINIMUM) | 16.BOARD MUST BE IDENTIFIED WITH APPROPRIATE VENDOR UL IDENTIFACTION MARK,DATE CODE. | 15.PCB VENDOR MUST BE UL QUALIFIED. | 10.ALL COPPER FEATURES ON THE BOARD ARE TO BE FINISHED WITH OSP COAT. | 11.THIS IS A 12 LAYER BOARD. VENDER TO PROVIDE BOARD STACK-UP FOR IMPEDANCE | APPROVAL PRIOR TO BOARD FABRICATION.STACK-UP AND IMPEDANCE TO INCLUDE COPPER | PLANTING THICKNESS ON OUTER LAYERS. | 12. | 14.PLATING : | 13. | OVER BARE COPPER PRIOR TO ANY PLATING FINISH PROCESSES | 2. ALL FINISHED BOARDS TO BE ELECTRICALLY TESTED. | 3. SILKSCREEN TO BE WHITE. NON-CONDUCTIVE , EPOXY INK OR EQUIVALENT. | 4. SOLDERMASK MATTE GREEN LIQUID PHOTO-IMAGABLE SMOBC SOLDERMASK TO BE APPLIED | 5. BOARD THICKNESS IS 0.0644" +/- 10% | 6 .NON-FUNCTIONAL PADS ON INTERNAL LAYERS MAY BE OMITTED. | 7 .TEARDROP TRACE ENTRY TO VIAS ON INTERNAL LAYERS, PROVIDED DRC RULES ARE MET. | 8 .ACCEPTABLE MINIMUM ANNULAR RING FOR VIA IS 0.001". | 9 .THIS IS A CONTROLLED IMPEDANCE BOARD. CONTROLS ARE AS FOLLOWS: | 1. MATERIAL:Halogen Free FR-4 Tg170 OR EQUIVALENT. THE USE OF SINGLE PLY CONSTRUCION IS OPTIONAL | NOTES: (UNLESS OTHERWISE SPECIFIED) | SUPPLIED ELECTRONIC DATA. | SHEET ONE OF THIS DOCUMENT IS FOR REFERENCE ONLY. FABRICATE USING THE | PLATED GOLD 0.254-0.508um[10-20u inch]) FOR GOLDEN FINGER | IMPEDANCE SHALL BE 85 OHMS +/-10% ON ALL DIFFENTIAL PAIRS WITH 5.3MIL/8.5MIL WIDTH/SPACING ON INNER LAYER. | IMPEDANCE SHALL BE 40 OHMS +/-10% ON ALL DIFFENTIAL PAIRS WITH 6.5MIL/5MIL WIDTH/SPACING ON OUTER LAYER. | IMPEDANCE SHALL BE 40 OHMS +/-10% ON ALL DIFFENTIAL PAIRS WITH 6MIL/4.5MIL WIDTH/SPACING ON INNER LAYER. | IMPEDANCE SHALL BE 85 OHMS +/-10% ON ALL DIFFENTIAL PAIRS WITH 5.3MIL/7.7MIL WIDTH/SPACING ON OUTER LAYER. | IMPEDANCE SHALL BE 100 OHMS +/-10% ON ALL DIFFENTIAL PAIRS WITH 4MIL/11.5MIL WIDTH/SPACING ON INNER LAYER. | IMPEDANCE SHALL BE 100 OHMS +/-10% ON ALL DIFFENTIAL PAIRS WITH 3.9MIL/8.6MIL WIDTH/SPACING ON OUTER LAYER. | IMPEDANCE SHALL BE 40 OHMS +/-10% ON OUTER LAYER WITH 6.5MIL AND INNER LAYER WITH 6MIL WIDTH. | IMPEDANCE SHALL BE 50 OHMS +/-10% ON OUTER LAYER WITH 4.3MIL AND INNER LAYER WITH 3.8MIL WIDTH. | THIEVING ON PLANE LAYERS. | OSP 0.254-0.6um[10-24uinch]) | Finish board thickness is 64.4mil+/-10% over gold finger
User.7: 4pcs | Fiducial(See Detail A) | 4Xdia3.175 +0.075 -0.000 Tooling hole | 4XR5.000 | 0.000 | 5.000 | 10.000 | 18.000 | 81.200 | 91.200 | 93.301 | 73.200 | 111.300 | 103.300 | 189.500 | 179.500 | 174.500 | 166.500 | 184.500 | 7.300 | 82.300 | 142.300 | 150.300 | 217.300 | 219.600 | 224.600 | 229.600 | 3.00 DIA. Soldermask clearance | 1.00 DIA. Fiducial | PCB outline dimension detail see gerber file | Top side view | Detail "A" | Unit: mm | Flow direction
User.9: 2 TO 2 | ASSY_BOT | BOTTOM SIDE VIEW
User.10: 1 TO 2 | ASSY_TOP | TOP SIDE VIEW
User.14: 0.0026" | 0.0050" | 0.0041" | 0.0040" | 10% | TOP SIDE SILKSCREEN (WHITE) | TOP SIDE SOLDERMASK | LAYER #1 TOP SIGNAL (FOIL 0.5OZ+PLATING ~ 1.8 OZ) | LAYER #2 L2-GND1 PLANE (1 OZ) | LAYER #3 L3-IN1 SIGNAL (1 OZ) | LAYER #4 L4-GND2 PLANE (1 OZ) | LAYER #5 L5-IN2 SIGNAL (1 OZ) | LAYER #6 L6-PWR1 PLANE (2 OZ) | LAYER #7 L7-PWR2 PLANE (2 OZ) | LAYER #8 L8-IN3 SIGNAL (1 OZ) | LAYER #9 L9-GND3 PLANE (1 OZ) | LAYER #10 L10-IN4 SIGNAL (1 OZ) | LAYER #11 L11-GND4 PLANE (1 OZ) | LAYER #12 BOTTOM SIGNAL (FOIL 0.5OZ+PLATING ~ 1.8 OZ) | BOTTOM SIDE SOLDERMASK | BOTTOM SIDE SILKSCREEN (WHITE) | + | - | 0.0644"
User.15: 2018/01/19 | LAYER | PROJECT | P/N:309.00149.015 | VER:015 | CAD | H/W | SHEET    OF | SIGNATURES | Mars | Jenna | DATA | T77O994T01 | GERBER | U | f | i | Space
User.16: 1 COMPONENT SIDE | 1     16
User.17: 2 | GND PLANE 1 | 16
User.18: 3 | INNER SIGNAL 1 | 16
User.19: 4 | GND PLANE 2 | 16
User.20: 5 | INNER SIGNAL 2 | 16
User.21: 6 | POWER PLANE 1 | 16
User.22: 7 | POWER PLANE 2 | 16
User.23: 8 | INNER SIGNAL 3 | 16
User.24: 9 | GND PLANE 3 | 16
User.25: 10 | INNER SIGNAL 4 | 16
User.26: 11 | GND PLANE 4 | 16
User.27: 2018/01/19 | SHEET | DWG NO | FSCM NO | SIZE | SCALE | DATE | SIGNATURES | CAD   Mars | ENGRG Jenna | ISSUED | UNLESS OTHERWISE SPECIFIED | DIMENSIONS ARE IN INCHES | TOLERANCES ON; | 2 PL DECIMALS +/- .010 | 3 PL DECIMALS +/- .005 | ANGLES +/- 5 | FRACTIONS + | APPROVED | REVISIONS | DESCRIPTION | REV | D | T77O994T01 | B | C | A | 1 | 2 | 3 | 4 | 5 | 6 | 7 | Space | i | f | U
User.29: BOT SIDE SILK SCREEN | 14 | 16
User.30: TOP SIDE SILKSCREEN | 13 | 16
User.31: BOT SIDE SOLDER PAST | 2
User.34: TOP SIDE SOLDER PAST | 1 | 2
User.35: BOT SIDE SOLDERMASK | 12 | 16
User.36: TOP SIDE SOLDERMASK | 11 | 16
User.37: GOLD PLATING FILM FOR BOT | 2
User.38: GOLD PLATING FILM FOR TOP | 1 | 2
User.39: 10 | BOTTOM SIDE | 12 | 16
User.44: FIGURE | FHS | 8.0 | 10.0 | 12.0 | 20.0 | 28.0 | 37.0 | 38.0 | 67.0 | 126.0 | 165.0 | 45.0 | 47.0 | 51.0 | 69.0 | 118.0 | 134.0 | DRILL CHART: TOP to BOTTOM | ALL UNITS ARE IN MILS | TOLERANCE | +2.0/-5.0 | +2.0/-7.0 | +3.0/-3.0 | +2.0/-2.0 | PLATED | NON-PLATED | QTY | 3745 | 93 | 42 | 230 | 32 | 1 | 2 | 4 | 3
